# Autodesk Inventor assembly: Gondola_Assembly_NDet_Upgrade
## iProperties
Shininess: 64.0
Length Units: 11272
Angle Units: 11279
Time Units: 11290
Mass Units: 11286
Length Display Precision: 3
Angle Display Precision: 2
Compacted: True
Part Number: Gondola_Assembly_NDet_Upgrade
Document SubType Name: Assembly
Created: 2004-08
Designer: John Blackburn
Manufacturer: Standard
Standards Organization: Custom
Density: 0.0
Volumn: 0.0
Area: 0.0
PropertySet Name: Model Information
Control State: 0
Master: False
Checked Out: False
Author: John Blackburn
